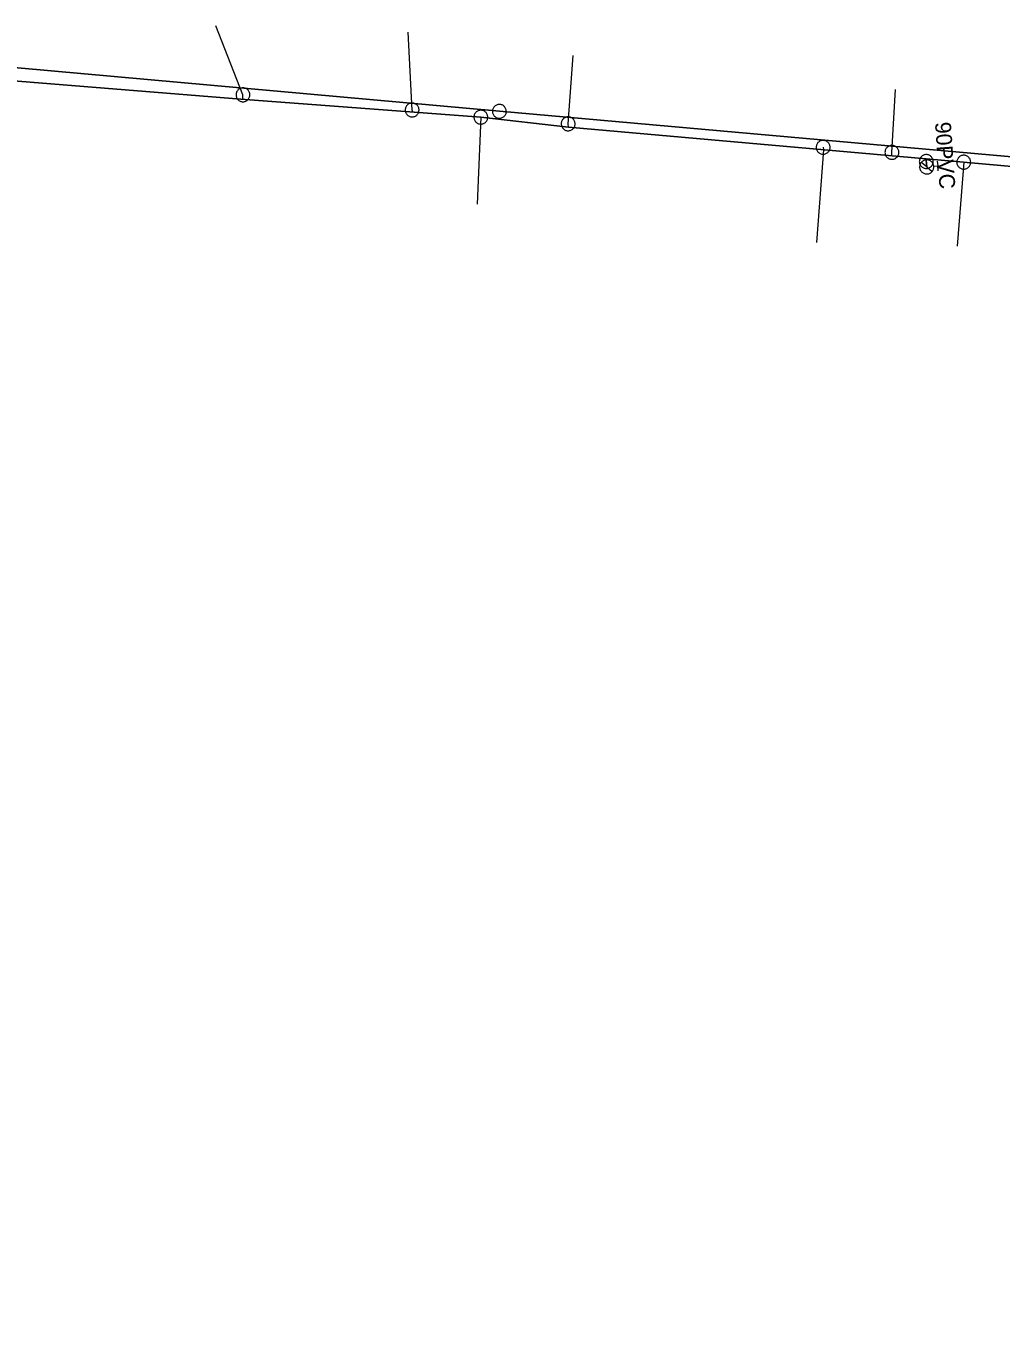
# Model space of a CAD drawing. Extents: x -741806 to -738704, y -1059275 to -1055387.
# Drawn here: x -740808.2 to -740746.7, y -1058132 to -1058050.1 of the extents above; entities that cross this region are included whole.
import ezdxf

# ---------------------------------------------------------------- set-up
doc = ezdxf.new("R2010")
doc.units = 0
doc.header["$LTSCALE"] = 0.4
for name, color, linetype, lineweight in [('2', 7, 'Continuous', 25), ('21', 7, 'Continuous', 13), ('3', 7, 'Continuous', 13), ('50', 7, 'Continuous', 13), ('51', 7, 'Continuous', 13), ('52', 7, 'Continuous', 25)]:
    doc.layers.add(name, color=color, linetype=linetype, lineweight=lineweight)
doc.layers.add('53', color=7, linetype='Continuous')

msp = doc.modelspace()

# ---------------------------------------------------------------- linework, layer by layer
at = {"layer": '2'}
msp.add_lwpolyline([(-740824.89, -1058051.27), (-740778.35, -1058055.46), (-740728.07, -1058059.94), (-740708.829, -1058061.48), (-740678.949, -1058063.95), (-740625.71, -1058070.179)], dxfattribs=at)
at = {"layer": '21'}
for p, q in [((-740779.522, -1058055.831), (-740779.741, -1058061.307)), ((-740749.048, -1058058.672), (-740749.467, -1058063.963))]:
    msp.add_line(p, q, dxfattribs=at)
for points in [[(-740794.536, -1058054.697), (-740794.53, -1058054.419), (-740796.25, -1058050.077)], [(-740783.805, -1058055.508), (-740783.859, -1058055.379), (-740784.109, -1058050.46)], [(-740773.993, -1058056.467), (-740774.01, -1058056.25), (-740773.695, -1058051.949)], [(-740753.585, -1058058.269), (-740753.579, -1058058.05), (-740753.361, -1058054.088)], [(-740757.92, -1058057.73), (-740757.9, -1058057.888), (-740758.348, -1058063.743)]]:
    msp.add_lwpolyline(points, dxfattribs=at)
at = {"layer": '3'}
msp.add_lwpolyline([(-740777.913, -1058055.499), (-740777.912, -1058055.454), (-740777.915, -1058055.409), (-740777.923, -1058055.363), (-740777.935, -1058055.32), (-740777.953, -1058055.277), (-740777.974, -1058055.236), (-740778, -1058055.198), (-740778.029, -1058055.163), (-740778.062, -1058055.131), (-740778.098, -1058055.103), (-740778.136, -1058055.079), (-740778.178, -1058055.058), (-740778.221, -1058055.043), (-740778.265, -1058055.031), (-740778.31, -1058055.025), (-740778.356, -1058055.023), (-740778.402, -1058055.027), (-740778.447, -1058055.034), (-740778.491, -1058055.047), (-740778.534, -1058055.064), (-740778.574, -1058055.085), (-740778.611, -1058055.11), (-740778.647, -1058055.14), (-740778.679, -1058055.172), (-740778.707, -1058055.209), (-740778.731, -1058055.248), (-740778.752, -1058055.288), (-740778.768, -1058055.332), (-740778.779, -1058055.376), (-740778.785, -1058055.422), (-740778.787, -1058055.467), (-740778.784, -1058055.512), (-740778.776, -1058055.558), (-740778.763, -1058055.602), (-740778.747, -1058055.644), (-740778.725, -1058055.685), (-740778.7, -1058055.723), (-740778.67, -1058055.759), (-740778.637, -1058055.79), (-740778.602, -1058055.818), (-740778.563, -1058055.842), (-740778.521, -1058055.863), (-740778.479, -1058055.879), (-740778.434, -1058055.89), (-740778.389, -1058055.896), (-740778.343, -1058055.898), (-740778.297, -1058055.895), (-740778.252, -1058055.887), (-740778.208, -1058055.874), (-740778.165, -1058055.857), (-740778.125, -1058055.836), (-740778.087, -1058055.811), (-740778.052, -1058055.781), (-740778.02, -1058055.749), (-740777.992, -1058055.712), (-740777.967, -1058055.673), (-740777.947, -1058055.633), (-740777.931, -1058055.589), (-740777.92, -1058055.545), (-740777.913, -1058055.5)], dxfattribs=at)
at = {"layer": '50'}
for p, q in [((-740751.383, -1058058.97), (-740751.728, -1058058.684)), ((-740751.383, -1058058.97), (-740751.043, -1058059.255)), ((-740750.938, -1058058.928), (-740750.688, -1058058.904)), ((-740750.717, -1058058.598), (-740750.688, -1058058.904)), ((-740750.66, -1058059.21), (-740750.688, -1058058.904))]:
    msp.add_line(p, q, dxfattribs=at)
msp.add_lwpolyline([(-740751.346, -1058059.412), (-740751.297, -1058059.405), (-740751.252, -1058059.396), (-740751.207, -1058059.378), (-740751.166, -1058059.357), (-740751.128, -1058059.335), (-740751.09, -1058059.304), (-740751.058, -1058059.272), (-740751.026, -1058059.236), (-740750.999, -1058059.198), (-740750.979, -1058059.156), (-740750.961, -1058059.113), (-740750.946, -1058059.069), (-740750.94, -1058059.022), (-740750.937, -1058058.976), (-740750.938, -1058058.93), (-740750.945, -1058058.884), (-740750.954, -1058058.84), (-740750.971, -1058058.795), (-740750.992, -1058058.753), (-740751.017, -1058058.712), (-740751.046, -1058058.676), (-740751.078, -1058058.642), (-740751.114, -1058058.612), (-740751.151, -1058058.587), (-740751.194, -1058058.564), (-740751.237, -1058058.546), (-740751.281, -1058058.534), (-740751.328, -1058058.524), (-740751.374, -1058058.523), (-740751.421, -1058058.521), (-740751.468, -1058058.529), (-740751.513, -1058058.541), (-740751.555, -1058058.556), (-740751.599, -1058058.576), (-740751.638, -1058058.602), (-740751.676, -1058058.63), (-740751.708, -1058058.663), (-740751.74, -1058058.698), (-740751.766, -1058058.738), (-740751.786, -1058058.778), (-740751.804, -1058058.823), (-740751.816, -1058058.868), (-740751.826, -1058058.912), (-740751.83, -1058058.961), (-740751.828, -1058059.007), (-740751.821, -1058059.053), (-740751.809, -1058059.098), (-740751.794, -1058059.143), (-740751.774, -1058059.184), (-740751.748, -1058059.225), (-740751.721, -1058059.26), (-740751.687, -1058059.295), (-740751.652, -1058059.324), (-740751.615, -1058059.351), (-740751.572, -1058059.371), (-740751.53, -1058059.391), (-740751.484, -1058059.404), (-740751.438, -1058059.41), (-740751.392, -1058059.414)], close=True, dxfattribs=at)
at = {"layer": '51'}
for points in [[(-740794.093, -1058054.419), (-740794.095, -1058054.374), (-740794.102, -1058054.329), (-740794.114, -1058054.284), (-740794.13, -1058054.242), (-740794.151, -1058054.201), (-740794.176, -1058054.162), (-740794.205, -1058054.127), (-740794.237, -1058054.094), (-740794.273, -1058054.066), (-740794.311, -1058054.041), (-740794.352, -1058054.02), (-740794.395, -1058054.003), (-740794.439, -1058053.991), (-740794.484, -1058053.984), (-740794.53, -1058053.982), (-740794.576, -1058053.984), (-740794.621, -1058053.991), (-740794.665, -1058054.003), (-740794.708, -1058054.02), (-740794.749, -1058054.041), (-740794.787, -1058054.066), (-740794.823, -1058054.094), (-740794.855, -1058054.127), (-740794.884, -1058054.162), (-740794.909, -1058054.201), (-740794.93, -1058054.242), (-740794.946, -1058054.284), (-740794.958, -1058054.329), (-740794.965, -1058054.374), (-740794.968, -1058054.42), (-740794.965, -1058054.465), (-740794.958, -1058054.51), (-740794.946, -1058054.555), (-740794.93, -1058054.597), (-740794.909, -1058054.638), (-740794.884, -1058054.677), (-740794.855, -1058054.712), (-740794.823, -1058054.745), (-740794.787, -1058054.773), (-740794.749, -1058054.798), (-740794.708, -1058054.819), (-740794.665, -1058054.836), (-740794.621, -1058054.847), (-740794.576, -1058054.855), (-740794.53, -1058054.857), (-740794.484, -1058054.855), (-740794.439, -1058054.847), (-740794.395, -1058054.836), (-740794.352, -1058054.819), (-740794.311, -1058054.798), (-740794.273, -1058054.773), (-740794.237, -1058054.745), (-740794.205, -1058054.712), (-740794.176, -1058054.677), (-740794.151, -1058054.638), (-740794.13, -1058054.597), (-740794.114, -1058054.555), (-740794.102, -1058054.51), (-740794.095, -1058054.465), (-740794.093, -1058054.42)], [(-740784.028, -1058054.976), (-740784.069, -1058054.995), (-740784.107, -1058055.019), (-740784.144, -1058055.048), (-740784.177, -1058055.079), (-740784.206, -1058055.114), (-740784.232, -1058055.152), (-740784.253, -1058055.192), (-740784.271, -1058055.235), (-740784.283, -1058055.279), (-740784.291, -1058055.324), (-740784.295, -1058055.369), (-740784.294, -1058055.416), (-740784.288, -1058055.461), (-740784.277, -1058055.505), (-740784.261, -1058055.548), (-740784.241, -1058055.59), (-740784.217, -1058055.629), (-740784.189, -1058055.664), (-740784.156, -1058055.697), (-740784.121, -1058055.727), (-740784.083, -1058055.752), (-740784.044, -1058055.775), (-740784.001, -1058055.791), (-740783.957, -1058055.804), (-740783.911, -1058055.812), (-740783.866, -1058055.816), (-740783.821, -1058055.814), (-740783.775, -1058055.808), (-740783.73, -1058055.797), (-740783.687, -1058055.781), (-740783.646, -1058055.761), (-740783.608, -1058055.737), (-740783.571, -1058055.709), (-740783.538, -1058055.678), (-740783.509, -1058055.642), (-740783.483, -1058055.604), (-740783.462, -1058055.564), (-740783.444, -1058055.521), (-740783.432, -1058055.477), (-740783.424, -1058055.433), (-740783.42, -1058055.387), (-740783.421, -1058055.341), (-740783.428, -1058055.296), (-740783.438, -1058055.251), (-740783.455, -1058055.208), (-740783.474, -1058055.166), (-740783.499, -1058055.128), (-740783.526, -1058055.092), (-740783.559, -1058055.059), (-740783.594, -1058055.029), (-740783.632, -1058055.004), (-740783.672, -1058054.982), (-740783.714, -1058054.965), (-740783.758, -1058054.952), (-740783.804, -1058054.944), (-740783.85, -1058054.941), (-740783.895, -1058054.942), (-740783.941, -1058054.949), (-740783.985, -1058054.96), (-740784.027, -1058054.975)], [(-740779.956, -1058055.78), (-740779.959, -1058055.825), (-740779.957, -1058055.871), (-740779.95, -1058055.917), (-740779.939, -1058055.96), (-740779.923, -1058056.003), (-740779.902, -1058056.045), (-740779.878, -1058056.083), (-740779.85, -1058056.119), (-740779.817, -1058056.151), (-740779.782, -1058056.181), (-740779.744, -1058056.206), (-740779.703, -1058056.228), (-740779.661, -1058056.245), (-740779.617, -1058056.257), (-740779.571, -1058056.264), (-740779.525, -1058056.267), (-740779.48, -1058056.266), (-740779.435, -1058056.259), (-740779.39, -1058056.247), (-740779.347, -1058056.231), (-740779.306, -1058056.21), (-740779.267, -1058056.186), (-740779.232, -1058056.157), (-740779.199, -1058056.126), (-740779.17, -1058056.09), (-740779.144, -1058056.051), (-740779.124, -1058056.012), (-740779.107, -1058055.968), (-740779.094, -1058055.924), (-740779.086, -1058055.879), (-740779.084, -1058055.834), (-740779.086, -1058055.788), (-740779.093, -1058055.742), (-740779.104, -1058055.699), (-740779.12, -1058055.656), (-740779.14, -1058055.614), (-740779.165, -1058055.576), (-740779.193, -1058055.54), (-740779.226, -1058055.508), (-740779.261, -1058055.478), (-740779.299, -1058055.453), (-740779.34, -1058055.431), (-740779.382, -1058055.415), (-740779.426, -1058055.402), (-740779.471, -1058055.395), (-740779.517, -1058055.392), (-740779.563, -1058055.394), (-740779.608, -1058055.4), (-740779.653, -1058055.412), (-740779.696, -1058055.428), (-740779.736, -1058055.449), (-740779.775, -1058055.473), (-740779.811, -1058055.502), (-740779.844, -1058055.533), (-740779.873, -1058055.569), (-740779.899, -1058055.608), (-740779.919, -1058055.647), (-740779.936, -1058055.691), (-740779.948, -1058055.735), (-740779.955, -1058055.779)], [(-740774.043, -1058055.814), (-740774.088, -1058055.819), (-740774.132, -1058055.83), (-740774.176, -1058055.845), (-740774.217, -1058055.865), (-740774.256, -1058055.889), (-740774.293, -1058055.917), (-740774.325, -1058055.948), (-740774.356, -1058055.983), (-740774.381, -1058056.021), (-740774.403, -1058056.061), (-740774.421, -1058056.103), (-740774.434, -1058056.147), (-740774.443, -1058056.192), (-740774.446, -1058056.238), (-740774.445, -1058056.284), (-740774.439, -1058056.329), (-740774.429, -1058056.374), (-740774.413, -1058056.417), (-740774.393, -1058056.458), (-740774.369, -1058056.497), (-740774.341, -1058056.533), (-740774.31, -1058056.567), (-740774.275, -1058056.596), (-740774.238, -1058056.622), (-740774.197, -1058056.644), (-740774.154, -1058056.662), (-740774.111, -1058056.675), (-740774.065, -1058056.683), (-740774.02, -1058056.687), (-740773.974, -1058056.686), (-740773.929, -1058056.68), (-740773.885, -1058056.669), (-740773.841, -1058056.654), (-740773.8, -1058056.634), (-740773.761, -1058056.61), (-740773.724, -1058056.582), (-740773.692, -1058056.551), (-740773.661, -1058056.516), (-740773.636, -1058056.478), (-740773.614, -1058056.438), (-740773.596, -1058056.396), (-740773.583, -1058056.351), (-740773.575, -1058056.307), (-740773.571, -1058056.261), (-740773.572, -1058056.215), (-740773.578, -1058056.17), (-740773.589, -1058056.125), (-740773.604, -1058056.082), (-740773.624, -1058056.041), (-740773.648, -1058056.002), (-740773.676, -1058055.966), (-740773.707, -1058055.932), (-740773.742, -1058055.903), (-740773.779, -1058055.876), (-740773.82, -1058055.855), (-740773.863, -1058055.837), (-740773.906, -1058055.824), (-740773.952, -1058055.816), (-740773.997, -1058055.812), (-740774.042, -1058055.814)], [(-740757.483, -1058057.73), (-740757.485, -1058057.685), (-740757.492, -1058057.64), (-740757.504, -1058057.595), (-740757.52, -1058057.553), (-740757.541, -1058057.512), (-740757.566, -1058057.473), (-740757.595, -1058057.438), (-740757.627, -1058057.405), (-740757.663, -1058057.377), (-740757.701, -1058057.352), (-740757.742, -1058057.331), (-740757.785, -1058057.314), (-740757.829, -1058057.302), (-740757.874, -1058057.295), (-740757.92, -1058057.293), (-740757.966, -1058057.295), (-740758.011, -1058057.302), (-740758.055, -1058057.314), (-740758.098, -1058057.331), (-740758.139, -1058057.352), (-740758.177, -1058057.377), (-740758.213, -1058057.405), (-740758.245, -1058057.438), (-740758.274, -1058057.473), (-740758.299, -1058057.512), (-740758.32, -1058057.553), (-740758.336, -1058057.595), (-740758.348, -1058057.64), (-740758.355, -1058057.685), (-740758.358, -1058057.731), (-740758.355, -1058057.776), (-740758.348, -1058057.821), (-740758.336, -1058057.866), (-740758.32, -1058057.908), (-740758.299, -1058057.949), (-740758.274, -1058057.988), (-740758.245, -1058058.023), (-740758.213, -1058058.056), (-740758.177, -1058058.084), (-740758.139, -1058058.109), (-740758.098, -1058058.13), (-740758.055, -1058058.147), (-740758.011, -1058058.158), (-740757.966, -1058058.166), (-740757.92, -1058058.168), (-740757.874, -1058058.166), (-740757.829, -1058058.158), (-740757.785, -1058058.147), (-740757.742, -1058058.13), (-740757.701, -1058058.109), (-740757.663, -1058058.084), (-740757.627, -1058058.056), (-740757.595, -1058058.023), (-740757.566, -1058057.988), (-740757.541, -1058057.949), (-740757.52, -1058057.908), (-740757.504, -1058057.866), (-740757.492, -1058057.821), (-740757.485, -1058057.776), (-740757.483, -1058057.731)], [(-740753.142, -1058058.05), (-740753.144, -1058058.005), (-740753.151, -1058057.96), (-740753.163, -1058057.915), (-740753.179, -1058057.873), (-740753.2, -1058057.832), (-740753.225, -1058057.793), (-740753.254, -1058057.758), (-740753.286, -1058057.725), (-740753.322, -1058057.697), (-740753.36, -1058057.672), (-740753.401, -1058057.651), (-740753.444, -1058057.634), (-740753.488, -1058057.622), (-740753.533, -1058057.615), (-740753.579, -1058057.613), (-740753.625, -1058057.615), (-740753.67, -1058057.622), (-740753.714, -1058057.634), (-740753.757, -1058057.651), (-740753.798, -1058057.672), (-740753.836, -1058057.697), (-740753.872, -1058057.725), (-740753.904, -1058057.758), (-740753.933, -1058057.793), (-740753.958, -1058057.832), (-740753.979, -1058057.873), (-740753.995, -1058057.915), (-740754.007, -1058057.96), (-740754.014, -1058058.005), (-740754.017, -1058058.051), (-740754.014, -1058058.096), (-740754.007, -1058058.141), (-740753.995, -1058058.186), (-740753.979, -1058058.228), (-740753.958, -1058058.269), (-740753.933, -1058058.308), (-740753.904, -1058058.343), (-740753.872, -1058058.376), (-740753.836, -1058058.404), (-740753.798, -1058058.429), (-740753.757, -1058058.45), (-740753.714, -1058058.467), (-740753.67, -1058058.478), (-740753.625, -1058058.486), (-740753.579, -1058058.488), (-740753.533, -1058058.486), (-740753.488, -1058058.478), (-740753.444, -1058058.467), (-740753.401, -1058058.45), (-740753.36, -1058058.429), (-740753.322, -1058058.404), (-740753.286, -1058058.376), (-740753.254, -1058058.343), (-740753.225, -1058058.308), (-740753.2, -1058058.269), (-740753.179, -1058058.228), (-740753.163, -1058058.186), (-740753.151, -1058058.141), (-740753.144, -1058058.096), (-740753.142, -1058058.051)], [(-740751.371, -1058059.064), (-740751.326, -1058059.058), (-740751.282, -1058059.046), (-740751.238, -1058059.03), (-740751.198, -1058059.01), (-740751.159, -1058058.986), (-740751.122, -1058058.957), (-740751.09, -1058058.925), (-740751.06, -1058058.89), (-740751.036, -1058058.852), (-740751.014, -1058058.812), (-740750.997, -1058058.769), (-740750.984, -1058058.724), (-740750.976, -1058058.68), (-740750.974, -1058058.634), (-740750.976, -1058058.588), (-740750.982, -1058058.542), (-740750.993, -1058058.498), (-740751.009, -1058058.456), (-740751.03, -1058058.414), (-740751.055, -1058058.375), (-740751.083, -1058058.34), (-740751.115, -1058058.307), (-740751.15, -1058058.278), (-740751.188, -1058058.252), (-740751.229, -1058058.231), (-740751.272, -1058058.214), (-740751.315, -1058058.202), (-740751.361, -1058058.194), (-740751.406, -1058058.191), (-740751.453, -1058058.193), (-740751.497, -1058058.2), (-740751.541, -1058058.211), (-740751.585, -1058058.227), (-740751.625, -1058058.247), (-740751.664, -1058058.271), (-740751.701, -1058058.3), (-740751.733, -1058058.332), (-740751.763, -1058058.367), (-740751.787, -1058058.405), (-740751.809, -1058058.446), (-740751.826, -1058058.488), (-740751.839, -1058058.533), (-740751.846, -1058058.578), (-740751.849, -1058058.623), (-740751.847, -1058058.669), (-740751.841, -1058058.715), (-740751.829, -1058058.759), (-740751.814, -1058058.802), (-740751.793, -1058058.843), (-740751.768, -1058058.882), (-740751.74, -1058058.917), (-740751.708, -1058058.95), (-740751.673, -1058058.979), (-740751.635, -1058059.005), (-740751.594, -1058059.026), (-740751.551, -1058059.043), (-740751.508, -1058059.055), (-740751.462, -1058059.063), (-740751.417, -1058059.066), (-740751.372, -1058059.064)], [(-740749.481, -1058058.632), (-740749.483, -1058058.677), (-740749.48, -1058058.723), (-740749.472, -1058058.769), (-740749.46, -1058058.812), (-740749.442, -1058058.854), (-740749.421, -1058058.896), (-740749.395, -1058058.933), (-740749.366, -1058058.969), (-740749.333, -1058059), (-740749.297, -1058059.028), (-740749.258, -1058059.053), (-740749.217, -1058059.073), (-740749.174, -1058059.089), (-740749.13, -1058059.1), (-740749.084, -1058059.106), (-740749.038, -1058059.108), (-740748.993, -1058059.105), (-740748.948, -1058059.097), (-740748.904, -1058059.084), (-740748.861, -1058059.067), (-740748.821, -1058059.045), (-740748.782, -1058059.021), (-740748.748, -1058058.991), (-740748.716, -1058058.958), (-740748.687, -1058058.922), (-740748.663, -1058058.883), (-740748.643, -1058058.842), (-740748.627, -1058058.799), (-740748.616, -1058058.754), (-740748.609, -1058058.709), (-740748.608, -1058058.664), (-740748.611, -1058058.618), (-740748.619, -1058058.573), (-740748.631, -1058058.529), (-740748.648, -1058058.487), (-740748.67, -1058058.445), (-740748.696, -1058058.408), (-740748.725, -1058058.372), (-740748.758, -1058058.341), (-740748.794, -1058058.313), (-740748.833, -1058058.288), (-740748.874, -1058058.268), (-740748.917, -1058058.253), (-740748.961, -1058058.241), (-740749.007, -1058058.235), (-740749.053, -1058058.233), (-740749.098, -1058058.237), (-740749.143, -1058058.244), (-740749.187, -1058058.257), (-740749.23, -1058058.274), (-740749.27, -1058058.296), (-740749.308, -1058058.32), (-740749.343, -1058058.35), (-740749.375, -1058058.383), (-740749.403, -1058058.419), (-740749.428, -1058058.458), (-740749.448, -1058058.499), (-740749.464, -1058058.542), (-740749.475, -1058058.587), (-740749.481, -1058058.631)]]:
    msp.add_lwpolyline(points, dxfattribs=at)
at = {"layer": '52'}
for points in [[(-740626.537, -1058069.271), (-740626.965, -1058069.033), (-740656.548, -1058067.382), (-740672.59, -1058065.485), (-740708.822, -1058062.591), (-740710.671, -1058062.095), (-740751.42, -1058058.46), (-740773.993, -1058056.467), (-740779.522, -1058055.831), (-740794.666, -1058054.688), (-740823.883, -1058052.338), (-740835.024, -1058060.166), (-740841.695, -1058066.003), (-740887.96, -1058170.041), (-740903.829, -1058207.8), (-740906.75, -1058213.899)], [(-740751.42, -1058058.46), (-740751.42, -1058058.54), (-740751.379, -1058058.97)]]:
    msp.add_lwpolyline(points, dxfattribs=at)

# ---------------------------------------------------------------- texts
at = {"layer": '53'}
msp.add_text('90PVC ', height=1, rotation=274, dxfattribs=at).set_placement((-740750.862, -1058056.164))

doc.saveas('drawing.dxf')
